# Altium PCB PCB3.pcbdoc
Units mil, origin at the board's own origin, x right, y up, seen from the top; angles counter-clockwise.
Board outline 3410 x 3405 mil, 2 copper layers (Top Layer, Bottom Layer); 8 components, 13 nets, 60 pads, 1 vias.
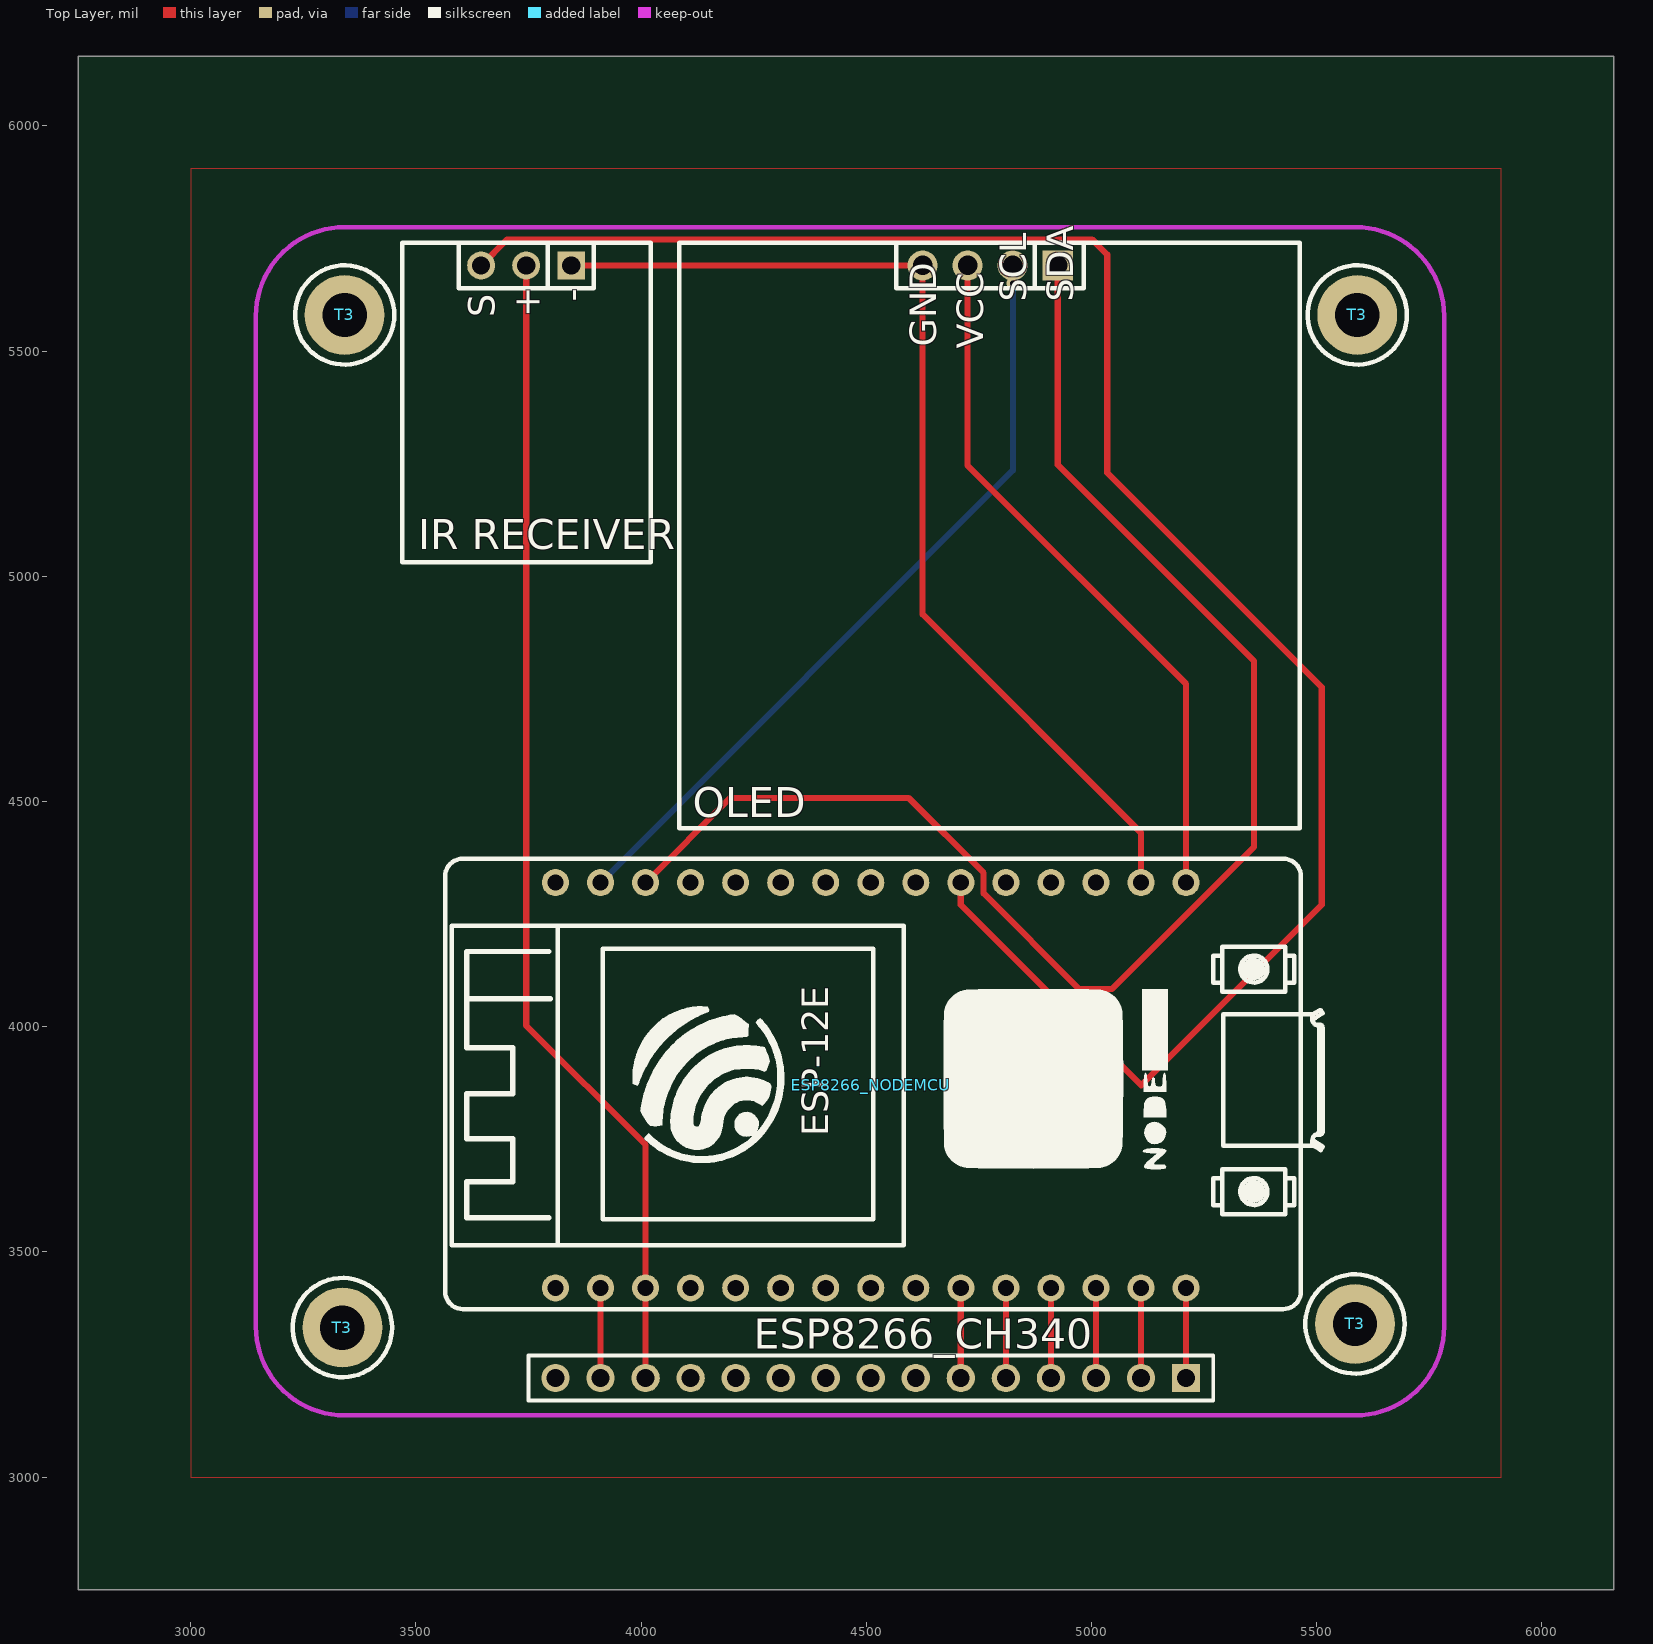
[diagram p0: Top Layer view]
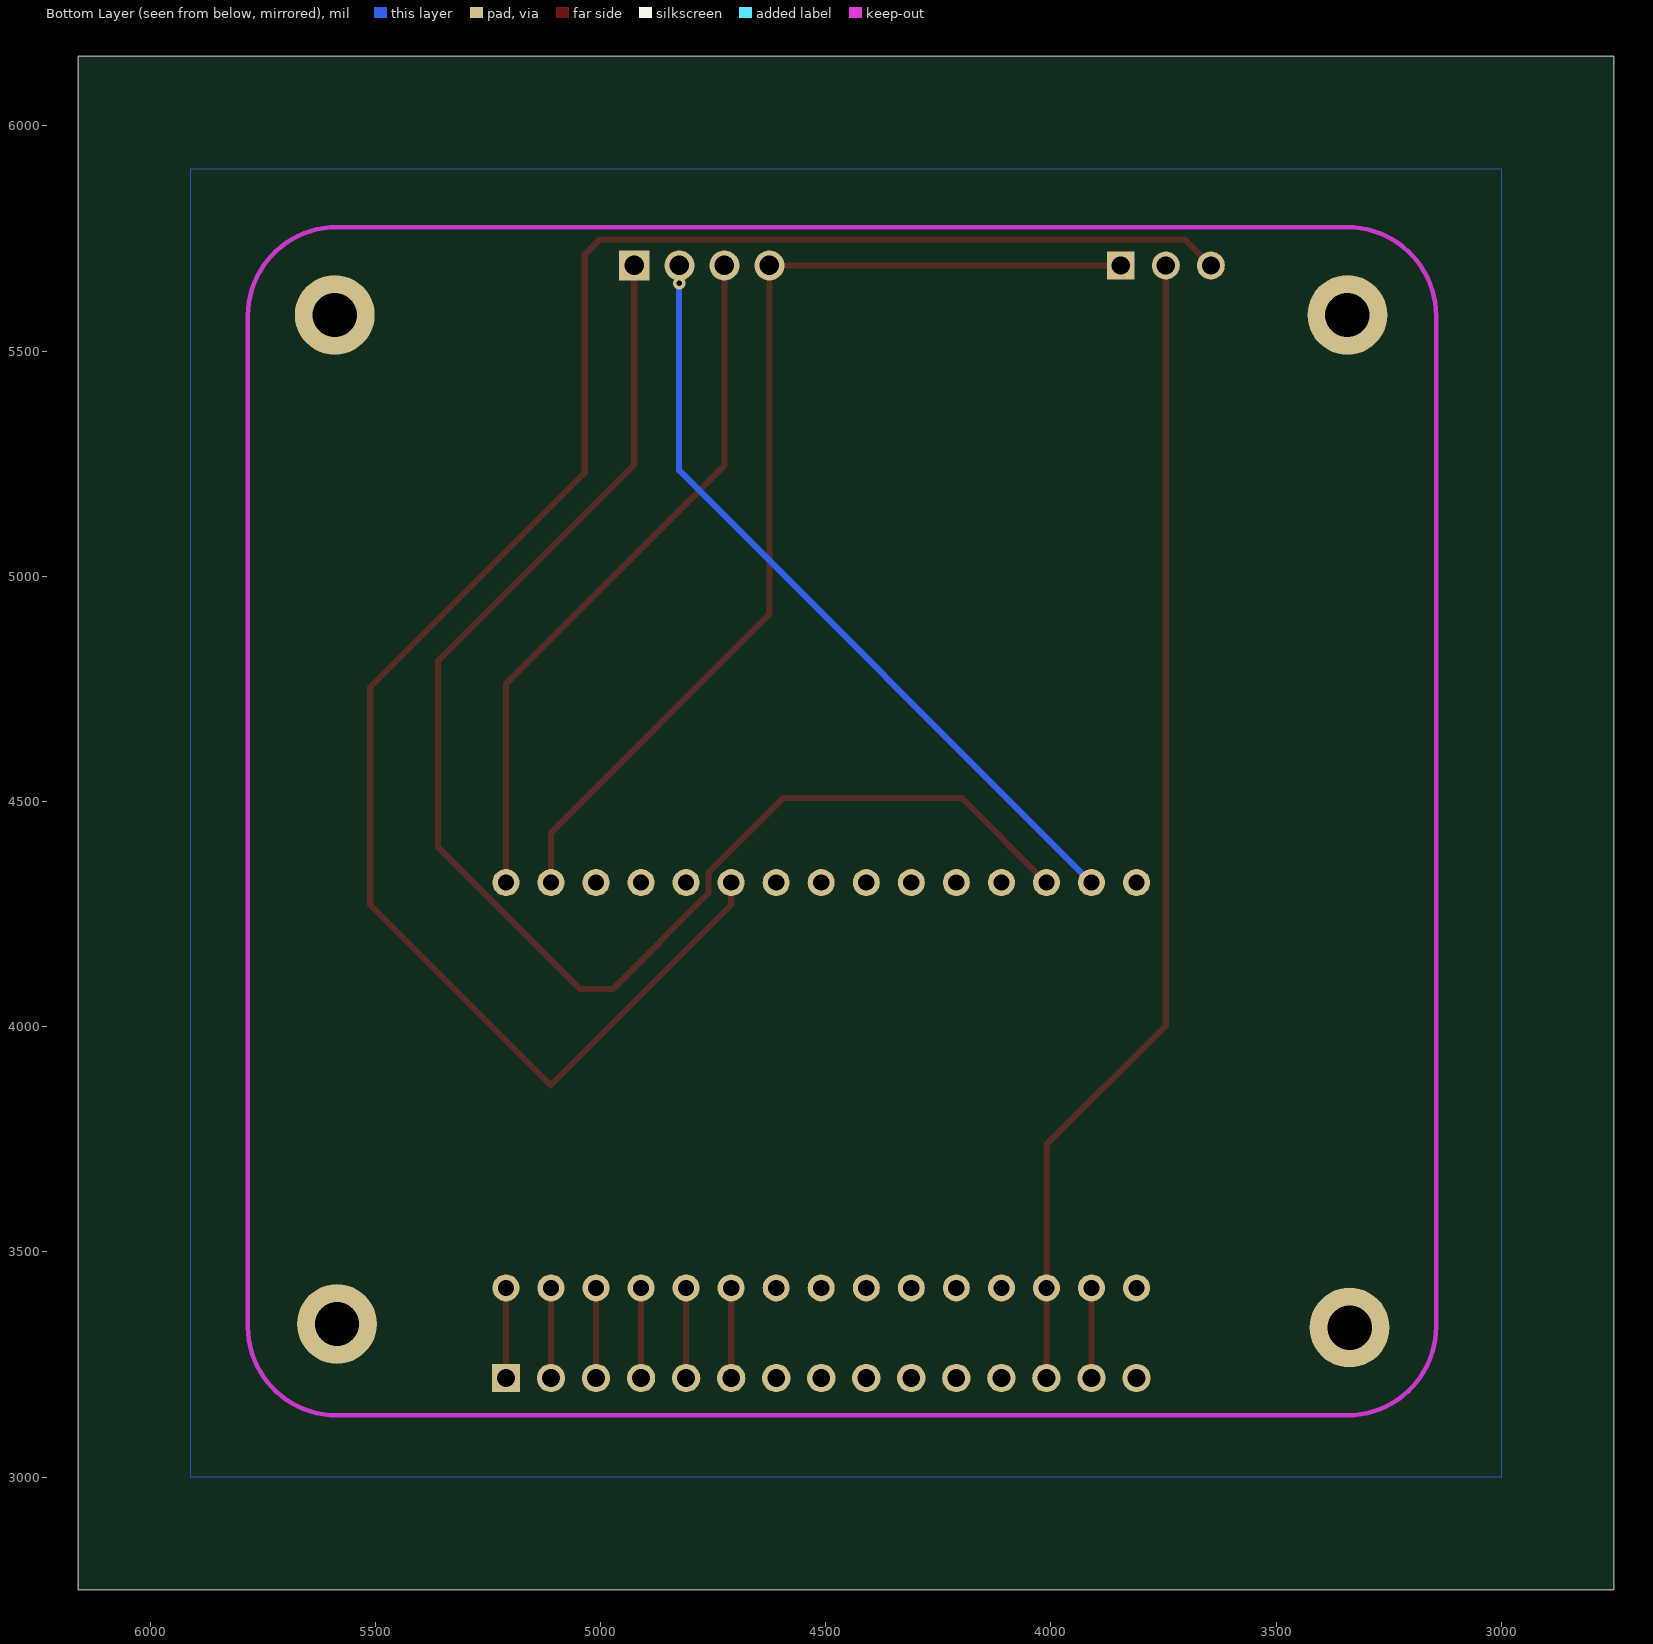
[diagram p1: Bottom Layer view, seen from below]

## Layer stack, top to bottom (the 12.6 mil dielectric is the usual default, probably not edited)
Top Layer: signal copper (thickness not stored)
Dielectric: dielectric 12.6, FR-4, Dk 4.8
Bottom Layer: signal copper (thickness not stored)

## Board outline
6160,2750 2750,2750 2750,6155 6160,6155

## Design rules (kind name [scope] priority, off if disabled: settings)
Clearance Default [All] p1: gap=7 ignorepadtopadclearanceinfootprint=FALSE except(0: Region-Region Region-Text Text-Text; 6: Track-Track Track-SMDPad SMDPad-SMDPad Track-THPad SMDPad-THPad THPad-THPad Track-Via SMDPad-Via THPad-Via Via-Via Track-Fill SMDPad-Fill THPad-Fill Via-Fill Fill-Fill Track-Region SMDPad-Region THPad-Region Via-Region Fill-Region Track-Poly SMDPad-Poly THPad-Poly Via-Poly Fill-Poly Region-Poly Poly-Poly Track-Text SMDPad-Text THPad-Text Via-Text Fill-Text Poly-Text Track-Sheet SMDPad-Sheet THPad-Sheet Via-Sheet Fill-Sheet Region-Sheet Poly-Sheet Text-Sheet Track-Hole SMDPad-Hole THPad-Hole Via-Hole Fill-Hole Region-Hole Poly-Hole Text-Hole Sheet-Hole)
Clearance Power [All] p1: gap=7 ignorepadtopadclearanceinfootprint=FALSE except(0: Region-Region Region-Text Text-Text; 6: Track-Sheet SMDPad-Sheet THPad-Sheet Via-Sheet Fill-Sheet Region-Sheet Poly-Sheet Text-Sheet Sheet-Hole; 6.3: Track-Track Track-SMDPad SMDPad-SMDPad Track-THPad SMDPad-THPad THPad-THPad Track-Via SMDPad-Via THPad-Via Via-Via Track-Fill SMDPad-Fill THPad-Fill Via-Fill Fill-Fill Track-Region SMDPad-Region THPad-Region Via-Region Fill-Region Track-Poly SMDPad-Poly THPad-Poly Via-Poly Fill-Poly Region-Poly Poly-Poly Track-Text SMDPad-Text THPad-Text Via-Text Fill-Text Poly-Text Track-Hole SMDPad-Hole THPad-Hole Via-Hole Fill-Hole Region-Hole Poly-Hole Text-Hole)
Clearance Wide [All] p1: gap=7 ignorepadtopadclearanceinfootprint=FALSE except(0: Region-Region Region-Text Text-Text; 6: Track-Sheet SMDPad-Sheet THPad-Sheet Via-Sheet Fill-Sheet Region-Sheet Poly-Sheet Text-Sheet Sheet-Hole; 7.1: Track-Track Track-SMDPad SMDPad-SMDPad Track-THPad SMDPad-THPad THPad-THPad Track-Via SMDPad-Via THPad-Via Via-Via Track-Fill SMDPad-Fill THPad-Fill Via-Fill Fill-Fill Track-Region SMDPad-Region THPad-Region Via-Region Fill-Region Track-Poly SMDPad-Poly THPad-Poly Via-Poly Fill-Poly Region-Poly Poly-Poly Track-Text SMDPad-Text THPad-Text Via-Text Fill-Text Poly-Text Track-Hole SMDPad-Hole THPad-Hole Via-Hole Fill-Hole Region-Hole Poly-Hole Text-Hole)
DiffPairsRouting differentialPair [All] p1: maxuncoupledlength=10 maxlimit=6 mostfreqgap=6 toplayer_minwidth=5 toplayer_prefwidth=10 toplayer_maxwidth=100 bottomlayer_minwidth=5 bottomlayer_prefwidth=10 bottomlayer_maxwidth=100
PasteMaskExpansion Common [All] p1:
PlaneConnect Default [All] p1: planeconnectstyle=Relief reliefexpansion=20 reliefentries=4 reliefconductorwidth=0 reliefairgap=10
PlaneConnect Power [All] p1: planeconnectstyle=Relief reliefexpansion=20 reliefentries=4 reliefconductorwidth=0 reliefairgap=10
PlaneConnect Wide [All] p1: planeconnectstyle=Relief reliefexpansion=20 reliefentries=4 reliefconductorwidth=0 reliefairgap=10
PolygonConnect gge880165 [All] p1: connectstyle=Relief reliefentries=4 polygonreliefangle="90 Angle" airgapwidth=10
PolygonConnect gge880153 [All] p1: connectstyle=Relief reliefentries=4 polygonreliefangle="90 Angle" airgapwidth=10
RoutingVias Default [All] p1: viastyle="Through Hole" holewidth=11.8 minholewidth=11.8 maxholewidth=2362 width=27.6 minwidth=27.6 maxwidth=3938
RoutingVias Power [All] p1: viastyle="Through Hole" holewidth=11.8 minholewidth=11.8 maxholewidth=2362 width=27.6 minwidth=27.6 maxwidth=3938
RoutingVias Wide [All] p1: viastyle="Through Hole" holewidth=11.8 minholewidth=11.8 maxholewidth=2362 width=47.2 minwidth=47.2 maxwidth=3938
SolderMaskExpansion Common [All] p1: useseparateexpansions=TRUE expansion=2 expansionbottom=2
Width Default [All] p1: maxlimit=1000 minlimit=14 preferedwidth=14
Width Power [All] p1: maxlimit=1000 minlimit=20 preferedwidth=20
Width Wide [All] p1: maxlimit=1000 minlimit=39 preferedwidth=39

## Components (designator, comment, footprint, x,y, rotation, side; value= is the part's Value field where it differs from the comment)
ESP8266_CH340 "HDR-F_2.54_1x15P" HDR-TH_15P-P2.54-V-F-1 4510,3220 r180 top
ESP8266_NODEMCU "NodeMCU8266" NODEMCU8266 5210,3420 r90 top
"IR RECEIVER" "HDR-F_2.54_1x3P" HDR-TH_3P-P2.54-V-F 3745,5690 r180 top
OLED "HDR-F_2.54_1x4P" HDR-TH_4P-P2.54-V-F 4775,5690 r180 top
T3 "M2" TH_BD4.0-D2.0 3341.85,5580.16 r0 top
T3 "M2" TH_BD4.0-D2.0 5590.16,5580.16 r0 top
T3 "M2" TH_BD4.0-D2.0 5585.16,3340 r0 top
T3 "M2" TH_BD4.0-D2.0 3336.85,3331.85 r0 top

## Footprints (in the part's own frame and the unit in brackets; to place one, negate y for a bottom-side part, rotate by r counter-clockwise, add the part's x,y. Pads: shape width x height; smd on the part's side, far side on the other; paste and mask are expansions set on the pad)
HDR-TH_3P-P2.54-V-F [mil]
  rect 62x62 hole 40.16: 1(-100,0)
  round 62 hole 40.16: 2(0,0) 3(100,0)
  silkscreen extent -150,-50 150,50
HDR-TH_4P-P2.54-V-F [mm]
  rect 1.7x1.7 hole 1.1: 1(-3.81,0)
  round 1.7 hole 1.1: 2(-1.27,0) 3(1.27,0) 4(3.81,0)
  silkscreen extent -5.29,-1.27 5.29,1.27
HDR-TH_15P-P2.54-V-F-1 [mm]
  rect 1.6x1.575 hole 1: 1(-17.78,0)
  round 1.6 hole 1: 2(-15.24,0) 3(-12.7,0) 4(-10.16,0) 5(-7.62,0) 6(-5.08,0) 7(-2.54,0) 8(0,0) 9(2.54,0) 10(5.08,0) 11(7.62,0) 12(10.16,0) 13(12.7,0) 14(15.24,0) 15(17.78,0)
  silkscreen extent -19.3,-1.27 19.3,1.27
NODEMCU8266 [mil]
  round 60 hole 36: 1(0,0) 2(0,100) 3(0,200) 4(0,300) 5(0,400) 6(0,500) 7(0,600) 8(0,700) 9(0,800) 10(0,900) 11(0,1000) 12(0,1100) 13(0,1200) 14(0,1300) 15(0,1400) 16(900,0) 17(900,100) 18(900,200) 19(900,300) 20(900,400) 21(900,500) 22(900,600) 23(900,700) 24(900,800) 25(900,900) 26(900,1000) 27(900,1100) 28(900,1200) 29(900,1300) 30(900,1400)
  silkscreen extent -47,-303 953,1645
TH_BD4.0-D2.0 [mm]
  round 4.5 hole 2.5: 1(0,0)
  silkscreen extent -2.8,-2.8 2.8,2.8

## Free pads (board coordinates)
  round 177.17 hole 98.43: 31(3336.85,3331.85) 31(3341.85,5580.16) 31(5585.16,3340) 31(5590.16,5580.16)

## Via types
v1: diameter 27.6, hole 11.8, Top Layer to Bottom Layer, 1 vias

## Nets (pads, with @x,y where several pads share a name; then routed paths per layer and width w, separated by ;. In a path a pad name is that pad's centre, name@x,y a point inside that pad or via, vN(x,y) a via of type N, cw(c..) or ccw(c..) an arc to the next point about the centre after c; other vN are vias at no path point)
5V: "IR RECEIVER.2" ESP8266_CH340.13 ESP8266_NODEMCU.13 | length 2579.8
  Top Layer w13.8: 3745,5690 3745,4002.5 4010,3737.5 ESP8266_NODEMCU.13 ESP8266_CH340.13
$1N678: ESP8266_NODEMCU.28 OLED.1 | length 3233.4
  Top Layer w13.8: ESP8266_NODEMCU.28 4197.98,4507.98 4593.8,4507.98 4760.44,4341.35 4760.44,4295.77 4972.65,4083.56 5045.34,4083.56 5360.92,4399.14 5360.92,4811.46 4925,5247.38 OLED.1
$1N683: 
$1N778: "IR RECEIVER.3" ESP8266_NODEMCU.21 | length 4251.3
  Top Layer w13.8: 3645,5690 3702.89,5747.89 5001.2,5747.89 5035,5714.09 5035,5230 5511.4,4753.6 5511.4,4270.7 5110.7,3870 4710,4270.7 ESP8266_NODEMCU.21
$1N868: ESP8266_CH340.1 ESP8266_NODEMCU.1 | length 200
  Top Layer w13.8: ESP8266_CH340.1 ESP8266_NODEMCU.1
$1N871: ESP8266_CH340.2 ESP8266_NODEMCU.2 | length 200
  Top Layer w13.8: ESP8266_CH340.2 ESP8266_NODEMCU.2
$1N876: ESP8266_CH340.3 ESP8266_NODEMCU.3 | length 200
  Top Layer w13.8: ESP8266_CH340.3 ESP8266_NODEMCU.3
$1N881: ESP8266_CH340.4 ESP8266_NODEMCU.4 | length 200
  Top Layer w13.8: ESP8266_CH340.4 ESP8266_NODEMCU.4
$1N886: ESP8266_CH340.5 ESP8266_NODEMCU.5 | length 200
  Top Layer w13.8: ESP8266_CH340.5 ESP8266_NODEMCU.5
$1N891: ESP8266_CH340.6 ESP8266_NODEMCU.6 | length 200
  Top Layer w13.8: ESP8266_CH340.6 ESP8266_NODEMCU.6
$1N902: ESP8266_CH340.14 ESP8266_NODEMCU.14 | length 200
  Top Layer w13.8: ESP8266_CH340.14 ESP8266_NODEMCU.14
GND: "IR RECEIVER.1" ESP8266_NODEMCU.17 OLED.4 | length 2350.9
  Top Layer w13.8: 3845,5690 OLED.4 4625,4915.58 5110,4430.58 ESP8266_NODEMCU.17
VCC: ESP8266_NODEMCU.16 OLED.3 | length 1570.9
  Top Layer w13.8: OLED.3 4725,5245.78 5210,4760.78 ESP8266_NODEMCU.16
pads on no net: ESP8266_CH340.7 ESP8266_CH340.8 ESP8266_CH340.9 ESP8266_CH340.10 ESP8266_CH340.11 ESP8266_CH340.12 ESP8266_CH340.15 ESP8266_NODEMCU.7 ESP8266_NODEMCU.8 ESP8266_NODEMCU.9 ESP8266_NODEMCU.10 ESP8266_NODEMCU.11 ESP8266_NODEMCU.12 ESP8266_NODEMCU.15 ESP8266_NODEMCU.18 ESP8266_NODEMCU.19 ESP8266_NODEMCU.20 ESP8266_NODEMCU.22 ESP8266_NODEMCU.23 ESP8266_NODEMCU.24 ESP8266_NODEMCU.25 ESP8266_NODEMCU.26 ESP8266_NODEMCU.27 ESP8266_NODEMCU.29 ESP8266_NODEMCU.30 OLED.2 T3.1
copper on no net: | length 1749.4
  Top Layer w13.8: 4825,5690 4825,5651.14 v1(4825.49,5650.66)
  Bottom Layer w13.8: 3910,4320 4825.49,5235.49 v1(4825.49,5650.66)

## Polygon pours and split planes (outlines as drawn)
GND on Top Layer (solid, remove dead copper): 3000,3000 5910,3000 5910,5905 3000,5905
GND on Bottom Layer (solid, remove dead copper, pour order 4): 3000,3000 5910,3000 5910,5905 3000,5905

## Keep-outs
Board Outline Layer:
  lines w10: 3145,3334.06 ccw(c3341.85,3334.06) 3341.85,3137.2 5585.94,3137.2 ccw(c5585.94,3334.06) 5782.8,3334.06 5782.8,5578.15 ccw(c5585.94,5578.15) 5585.94,5775 3341.85,5775 ccw(c3341.85,5578.15) 3145,5578.15 3145,3334.06

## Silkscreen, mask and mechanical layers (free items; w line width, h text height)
Top Silkscreen Layer:
  lines w10: 3470,5031.34 4021.18,5031.34 4021.18,5740 3470,5740 3470,5031.34 ; 4085,4440.79 5462.95,4440.79 5462.95,5740 4085,5740 4085,4440.79
  text "-" at 3875,5610 h59.06 r90
  text "SCL" at 4855,5610 h59.06 r90
  text "SDA" at 4959.53,5609.48 h59.06 r90
  text "S" at 3675,5575 h59.06 r90
  text "+" at 3775,5575 h59.06 r90
  text "GND" at 4655,5510 h59.06 r90
  text "VCC" at 4760,5505 h59.06 r90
